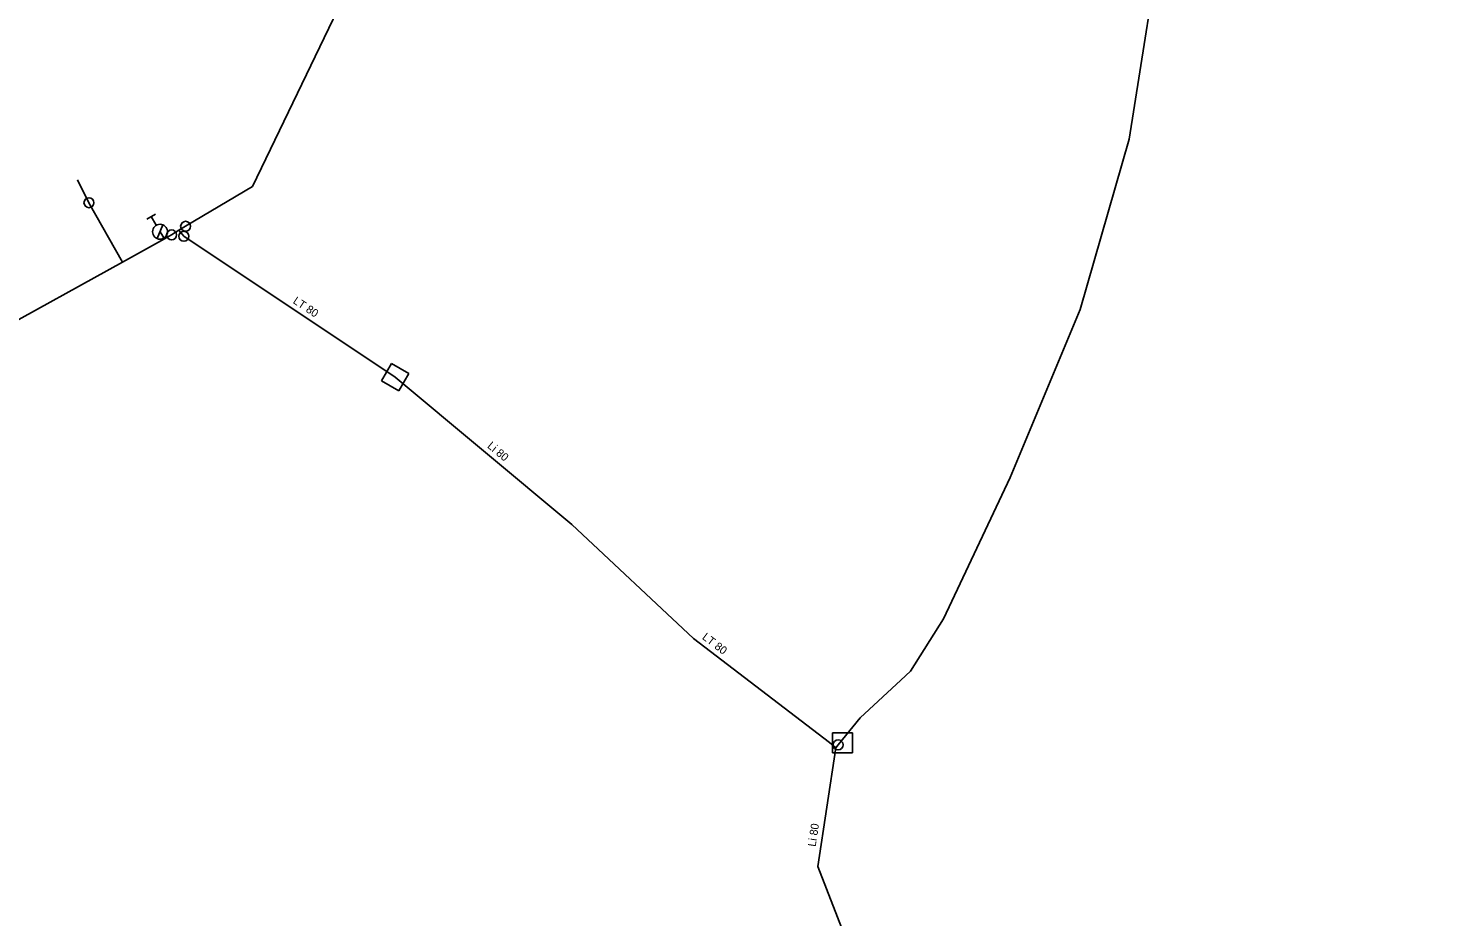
# Model space of a CAD drawing. Extents: x -783658 to -783200, y -1065250 to -1064865.
# Drawn here: x -783531.5 to -783460.5, y -1065101.7 to -1065057.3 of the extents above; entities that cross this region are included whole.
import ezdxf

# ---------------------------------------------------------------- set-up
doc = ezdxf.new("R2010")
doc.units = 0
for name, color, linetype in [('Hydranty', 7, 'Continuous'), ('Popis vodovodních řadů', 7, 'Continuous'), ('Vod přípojky-voda pitná', 7, 'Continuous'), ('Vodovodní řad', 7, 'Continuous'), ('Vodovodní šachty', 7, 'Continuous'), ('Vodovodní šoupata', 7, 'Continuous')]:
    doc.layers.add(name, color=color, linetype=linetype)

msp = doc.modelspace()

# ---------------------------------------------------------------- linework, layer by layer
at = {"layer": 'Hydranty'}
for p, q in [((-783525.574, -1065066.847), (-783525.141, -1065066.597)), ((-783525.108, -1065067.155), (-783525.358, -1065066.722)), ((-783525.059, -1065067.827), (-783524.78, -1065067.131))]:
    msp.add_line(p, q, dxfattribs=at)
msp.add_circle((-783524.92, -1065067.48), 0.375, dxfattribs=at)
at = {"layer": 'Vod přípojky-voda pitná'}
msp.add_lwpolyline([(-783526.8, -1065069), (-783528.47, -1065066.03), (-783529.05, -1065064.89)], dxfattribs=at)
at = {"layer": 'Vodovodní řad'}
for points in [[(-783478.79, -1064908.13), (-783497.07, -1064975.35), (-783507.36, -1065030.81), (-783511.11, -1065046.15), (-783520.3, -1065065.23), (-783523.64, -1065067.21)], [(-783491.03, -1065093.11), (-783489.92, -1065091.75), (-783487.89, -1065089.87), (-783487.42, -1065089.43), (-783485.77, -1065086.82), (-783482.43, -1065079.75), (-783478.94, -1065071.37), (-783476.48, -1065062.86), (-783474.66, -1065051.39), (-783471.19, -1065033.53), (-783470.69, -1065027.63), (-783469.73, -1065006.7), (-783468.34, -1064991.83), (-783465.19, -1064970.59), (-783461.04, -1064957), (-783460.47, -1064955.35)], [(-783524.92, -1065067.48), (-783524.7, -1065067.84)], [(-783524.34, -1065067.64), (-783524.7, -1065067.84)], [(-783524.34, -1065067.64), (-783523.98, -1065067.41)], [(-783523.98, -1065067.41), (-783523.64, -1065067.21)], [(-783523.98, -1065067.41), (-783523.73, -1065067.71)], [(-783523.73, -1065067.71), (-783513.17, -1065074.75)], [(-783524.7, -1065067.84), (-783526.8, -1065069), (-783533.26, -1065072.56), (-783560.3, -1065088.12)], [(-783513.17, -1065074.75), (-783504.34, -1065082.1)], [(-783504.34, -1065082.1), (-783498.26, -1065087.8), (-783491.46, -1065092.99), (-783491.15, -1065093.26)], [(-783491.15, -1065093.26), (-783492.05, -1065099.19), (-783490.62, -1065102.82), (-783490.69, -1065103)], [(-783491.15, -1065093.26), (-783491.03, -1065093.11)]]:
    msp.add_lwpolyline(points, dxfattribs=at)
at = {"layer": 'Vodovodní šachty'}
for p, q in [((-783513.353, -1065074.067), (-783513.853, -1065074.933)), ((-783512.487, -1065074.567), (-783513.353, -1065074.067)), ((-783512.987, -1065075.433), (-783512.487, -1065074.567)), ((-783513.853, -1065074.933), (-783512.987, -1065075.433)), ((-783490.31, -1065092.5), (-783491.31, -1065092.5)), ((-783491.31, -1065092.5), (-783491.31, -1065093.5)), ((-783490.31, -1065093.5), (-783490.31, -1065092.5)), ((-783491.31, -1065093.5), (-783490.31, -1065093.5))]:
    msp.add_line(p, q, dxfattribs=at)
at = {"layer": 'Vodovodní šoupata'}
for centre in [(-783528.47, -1065066.03), (-783523.64, -1065067.21), (-783524.34, -1065067.64), (-783523.73, -1065067.71), (-783491.03, -1065093.11)]:
    msp.add_circle(centre, 0.25, dxfattribs=at)

# ---------------------------------------------------------------- texts
at = {"layer": 'Popis vodovodních řadů'}
for s, rotation, p in [('LT 80', 326.30993, (-783518.311, -1065071.022)), ('Li 80', 320.22636, (-783508.595, -1065078.233)), ('LT 80', 322.64785, (-783497.857, -1065087.793)), ('Li 80', 81.37004, (-783492.154, -1065098.212))]:
    msp.add_text(s, height=0.4, rotation=rotation, dxfattribs=at).set_placement(p)

doc.saveas('drawing.dxf')
